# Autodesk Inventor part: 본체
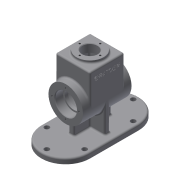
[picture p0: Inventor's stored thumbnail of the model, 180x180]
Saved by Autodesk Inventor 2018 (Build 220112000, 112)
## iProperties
Created: 2019-01
Part Number: 본체
Material: 알루미늄 6061
Document SubType Name: Modeling
Designer: mduedu
Density: 2.71 g/cm^3
Appearance: 기본값
Mass: 1057.71 g
Surface Area: 916.19 cm^2
Volume: 390.3 cm^3
Author: mduedu
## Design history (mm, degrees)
sketch "스케치1"
  geometry: C1 r 32 at (0, 0); 1 further point
  constraints: 1 centre point, 1 coincident
  dimensions: "d0" = 64 diameter of C1
extrude "돌출1" new body sketch "스케치1" stored distance "d1" = 90; taper "d2" = 0 deg
sketch "스케치2"
  geometry: L1 (0, 32)-(60, 32); L2 (60, 32)-(60, -32); L3 (60, -32)-(0, -32); L4 (0, -32)-(0, 32); C1 r 32 at (0, 0) reference; 2 further points
  constraints: 8 end point, 2 parallel, 1 coincident, 1 horizontal, 1 midpoint, 1 perpendicular, 1 tangent
  dimensions: "d5" = 60 distance between parallel lines of L4 L2
extrude "돌출2" join sketch "스케치2" stored distance "d7" = 64; taper "d8" = 0 deg
sketch "스케치3"
  geometry: C1 r 25 at (32, 32); 1 further point
  constraints: 1 centre point, 1 coincident
  dimensions: "d9" = 50 diameter of C1
extrude "돌출3" join sketch "스케치3" distance "d10" = 5; taper "d11" = 0 deg
sketch "스케치4"
  geometry: L1 (50, 25)-(0, 25); L2 (0, 25)-(0, -25); L3 (0, -25)-(50, -25); L4 (50, -25)-(50, 25); L5 (65, -25)-(65, 25) reference; A1 r 25 centre (0, 0) between (0, 25) and (0, -25); A2 r 25 centre (0, 0) between (0, -25) and (0, 25); 2 further points
  constraints: 8 end point, 4 point on circle, 2 centre point, 2 coincident, 2 parallel, 1 horizontal, 1 midpoint, 1 perpendicular, 1 tangent
  dimensions: "d12" = 50 diameter of A1; "d13" = 15 distance between parallel lines of L4 L5
extrude "돌출4" cut sketch "스케치4" stored distance "d14" = 48; taper "d15" = 0 deg
sketch "스케치5"
  geometry: C1 r 20 at (0, 0); 1 further point
  constraints: 1 centre point, 1 coincident
  dimensions: "d16" = 40 diameter of C1
extrude "돌출5" cut sketch "스케치5" distance "d17" = 15; taper "d18" = 0 deg
sketch "스케치6"
  geometry: C1 r 17 at (0, 0); 1 further point
  constraints: 1 centre point, 1 coincident
  dimensions: "d19" = 34 diameter of C1
extrude "돌출6" cut sketch "스케치6" extent not by distance; stored distance "d20" = 15; taper "d21" = 0 deg
fillet "모깎기1" dims "d22" = 0.3
fillet "모깎기2" dims "d23" = 3
fillet "모깎기3" dims "d24" = 3
fillet "모깎기4" dims "d25" = 3
fillet "모깎기5" dims "d26" = 3
fillet "모깎기6" dims "d27" = 3
sketch "스케치7"
  geometry: C1 r 14 at (0, 0); 1 further point
  constraints: 1 centre point, 1 coincident
  dimensions: "d28" = 28 diameter of C1
extrude "돌출7" cut sketch "스케치7" stored distance "d29" = 15; taper "d30" = 0 deg
chamfer "모따기1" distance "d31" = 1; stored, may be unused: second distance "d32" = 2, angle "d33" = 45 deg
chamfer "모따기2" distance "d34" = 1; stored, may be unused: second distance "d35" = 2, angle "d36" = 45 deg
node "작업 평면1"
sketch "스케치8"
  geometry: L1 (45, 45)-(-45, 45); L2 (-45, 45)-(-45, -45); L3 (-45, -45)-(45, -45); L4 (45, -45)-(45, 45); L5 (45, 45)-(-45, -45); L6 (-45, 45)-(45, -45); A1 r 45 centre (45, 0) between (45, -45) and (45, 45); A2 r 45 centre (-45, 0) between (-45, 45) and (-45, -45); A3 r 45 centre (45, 0) between (0, 0) and (45, -45); A4 r 45 centre (45, 0) between (0, 0) and (0, 0); A5 r 45 centre (45, 0) between (45, 45) and (0, 0); A6 r 45 centre (-45, 0) between (0, 0) and (-45, 45); A7 r 45 centre (-45, 0) between (-45, -45) and (0, 0); 1 further point
  constraints: 14 point on circle, 12 end point, 7 centre point, 7 midpoint, 2 parallel, 1 horizontal, 1 perpendicular
  dimensions: "d99" = 90 distance between parallel lines of L1 L3; "d101" = 90 distance between parallel lines of L2 L4
extrude "돌출8" join sketch "스케치8" distance "d41" = 10; taper "d42" = 0 deg
sketch "스케치9"
  geometry: L1 (-35, 5)-(35, 5); L2 (35, 5)-(35, -5); L3 (35, -5)-(-35, -5); L4 (-35, -5)-(-35, 5); 3 further points
  constraints: 8 end point, 2 midpoint, 2 parallel, 1 horizontal, 1 horizontal alignment, 1 perpendicular, 1 vertical alignment
  dimensions: "d52" = 10 distance of L1.end L2.end; "d54" = 70 distance of L1.start L1.end
extrude "돌출9" join sketch "스케치9" stored distance "d50" = 10; taper "d51" = 0 deg
sketch "스케치10"
  geometry: L1 (0, -25)-(47, -25) reference; L2 (50, -22)-(50, -14) reference; L3 (50, -14)-(64, -14) reference; L4 (64, -14)-(65, -15) reference; L5 (65, -15)-(65, -25) reference; L6 (65, -25)-(63, -25) reference; L7 (60, -28)-(60, -29) reference; L8 (57, -32)-(0, -32) reference; L9 (-31.607, -5)-(-55, -5) reference; L10 (-55, -5)-(-55, -45) reference; L11 (-65, -45)-(-65, 45) reference; L12 (-55, 45)-(-55, 5) reference; L13 (-55, 5)-(-31.607, 5) reference; L14 (0, 32)-(57, 32) reference; L15 (60, 29)-(60, 28) reference; L16 (63, 25)-(65, 25) reference; L17 (65, 25)-(65, 15) reference; L18 (65, 15)-(64, 14) reference; L19 (64, 14)-(50, 14) reference; L20 (50, 14)-(50, 22) reference; L21 (47, 25)-(0, 25) reference; L22 (-55, -45)-(-65, -45) reference; L23 (-65, 45)-(-55, 45) reference; L24 (0, 32)-(-55, 32); A1 r 25 centre (0, 0) between (0, 25) and (0, -25) reference; A2 r 3 centre (47, -22) between (47, -25) and (50, -22) reference; A3 r 3 centre (63, -28) between (63, -25) and (60, -28) reference; A4 r 3 centre (57, -29) between (57, -32) and (60, -29) reference; A5 r 32 centre (0, 0) between (-31.607, -5) and (0, -32) reference; A6 r 32 centre (0, 0) between (0, 32) and (-31.607, 5) reference; A7 r 3 centre (57, 29) between (60, 29) and (57, 32) reference; A8 r 3 centre (63, 28) between (60, 28) and (63, 25) reference; A9 r 3 centre (47, 22) between (50, 22) and (47, 25) reference
  constraints: 2 end point, 1 perpendicular, 1 point on line, 1 tangent
feature "리브1" sketch "스케치10" dims "d57" = 1, "d58" = 10, "d59" = 0, "d60" = 0, "d61" = 1, "d62" = 1
fillet "모깎기7" dims "d63" = 3
fillet "모깎기11" dims "d102" = 3
fillet "모깎기8" dims "d64" = 3
sketch "스케치11"
  geometry: L1 (8, -29)-(8, -8) reference; L2 (-8, -8)-(-8, -29) reference; L3 (-32, -8)-(-8, -8) reference; L4 (-38, 2)-(-38, -2) reference; L5 (-8, 8)-(-32, 8) reference; L6 (-8, 29)-(-8, 8) reference; L7 (8, 8)-(8, 29) reference; L8 (32, 8)-(8, 8) reference; L9 (38, -2)-(38, 2) reference; L10 (8, -8)-(32, -8) reference; L11 (-2, -35)-(2, -35) reference; L12 (2, 35)-(-2, 35) reference; L13 (-45, -45)-(45, -45) reference; L14 (45, 45)-(-45, 45) reference; L15 (-45, -35)-(45, -35); L16 (45, 35)-(-45, 35); A1 r 6 centre (-32, -2) between (-38, -2) and (-32, -8) reference; A2 r 6 centre (-32, 2) between (-32, 8) and (-38, 2) reference; A3 r 6 centre (32, 2) between (38, 2) and (32, 8) reference; A4 r 6 centre (32, -2) between (32, -8) and (38, -2) reference; A5 r 6 centre (2, -29) between (2, -35) and (8, -29) reference; A6 r 6 centre (-2, -29) between (-8, -29) and (-2, -35) reference; A7 r 6 centre (-2, 29) between (-2, 35) and (-8, 29) reference; A8 r 6 centre (2, 29) between (8, 29) and (2, 35) reference; A9 r 45 centre (-45, 0) between (-45, 45) and (-45, -45) reference; A10 r 45 centre (45, 0) between (45, -45) and (45, 45) reference; A11 r 35 centre (-45, 0) between (-45, 35) and (-45, -35); A12 r 35 centre (45, 0) between (45, -35) and (45, 35); 7 further points
  constraints: 6 point on circle, 4 coincident, 4 end point, 2 centre point, 3 other
  dimensions: "d103" = 10 distance between parallel lines of L16 L14
hole "구멍1" sketch "스케치11" at (-45, 35), (-80, 0), (-45, -35), (45, -35), (80, 0), (45, 35) diameter "d66" = 9; stored, may be unused: countersink angle "d70" = 90 deg, drill point angle "d72" = 118 deg; dims "d67" = 6, "d68" = 4, "d69" = 2, "d71" = 8
fillet "모깎기10" dims "d73" = 3
sketch "스케치12"
  geometry: L1 (-3, 57)-(-3, 19.596) reference; 2 further points
  constraints: 1 other
  dimensions: "d74" = 32 distance from line of point (29, 45) L1; "d75" = 45 distance of point (29, 45) point (29, 0)
feature "엠보싱1" sketch "스케치12" dims "d12" = 50, "d13" = 15, "d76" = 0.5, "d77" = 0
sketch "스케치13"
  geometry: 4 further points
  constraints: 4 other
hole "구멍2" sketch "스케치13" at (-25, 0), (0, -25), (25, 0), (0, 25) diameter "d78" = 3.242; stored, may be unused: countersink angle "d82" = 90 deg, drill point angle "d84" = 120 deg; dims "d79" = 7, "d80" = 4, "d81" = 2, "d83" = 9
sketch "스케치14"
  geometry: 4 further points
  constraints: 4 other
hole "구멍3" sketch "스케치14" at (-25, 0), (0, -25), (25, 0), (0, 25) diameter "d85" = 3.242; stored, may be unused: countersink angle "d89" = 90 deg, drill point angle "d91" = 120 deg; dims "d86" = 7, "d87" = 4, "d88" = 2, "d90" = 9
sketch "스케치15"
  geometry: 4 further points
  constraints: 4 other
hole "구멍4" sketch "스케치15" at (0, -19), (19, 0), (0, 19), (-19, 0) diameter "d92" = 3.242; stored, may be unused: countersink angle "d96" = 90 deg, drill point angle "d98" = 120 deg; dims "d93" = 8, "d94" = 4, "d95" = 2, "d97" = 10
node "솔리드1"
mirror "대칭1"
mirror "대칭2"
node "투영된 루프1"
node "투영된 루프2"
node "절단 모서리 투영1"
node "절단 모서리 투영2"
other parameters: "d37" = -65
